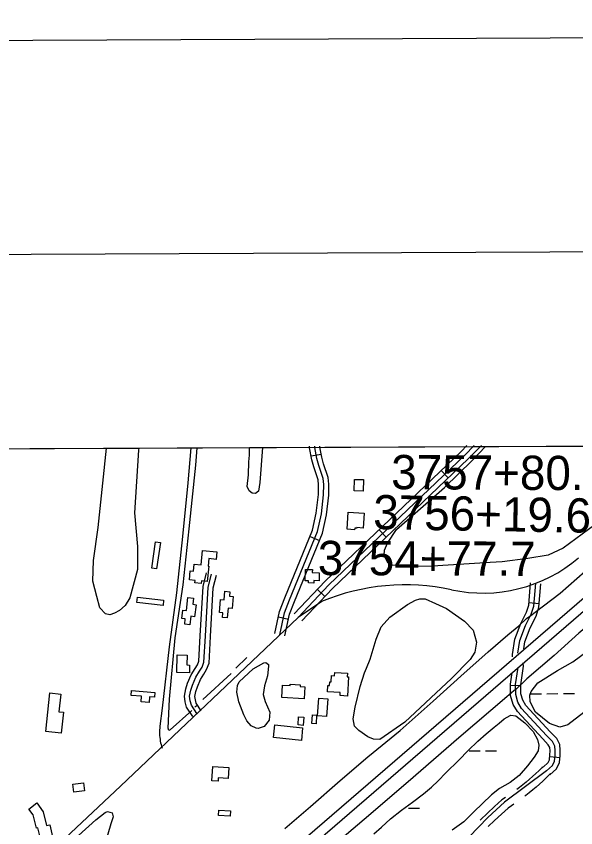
# Model space of a CAD drawing. Extents: x 3424494 to 3462436, y 522220 to 547718.
# Drawn here: x 3445950 to 3447583, y 544764 to 547135 of the extents above; entities that cross this region are included whole.
import ezdxf

# ---------------------------------------------------------------- set-up
doc = ezdxf.new("R2010")
doc.units = 0
for name, color, linetype in [('G-ANNO-NPLT', 7, 'Continuous'), ('V-ANNO-SYMB', 7, 'Continuous'), ('V-BLDG-OTLN', 7, 'Continuous'), ('V-GRID-FRAM', 7, 'Continuous'), ('V-LEVE-TOET', 7, 'Continuous'), ('V-RIVR-EDGE', 7, 'Continuous'), ('V-ROAD-CNTR', 7, 'Continuous'), ('V-SITE-VEGE', 7, 'Continuous'), ('V-SURV-IDEN', 7, 'Continuous'), ('V-SURV-LINE', 7, 'Continuous'), ('V-TOPO-SHOR', 7, 'Continuous'), ('V-WETL-SWMP', 7, 'Continuous')]:
    doc.layers.add(name, color=color, linetype=linetype)

msp = doc.modelspace()

# ---------------------------------------------------------------- linework, layer by layer
at = {"layer": 'G-ANNO-NPLT'}
msp.add_lwpolyline([(3425186.3, 522803.1), (3461852.6, 522968.4), (3461743.6, 547134.8), (3425077.3, 546969.5)], close=True, dxfattribs=at)
at = {"layer": 'V-ANNO-SYMB'}
msp.add_lwpolyline([(3427933.6, 523440.5), (3461016.5, 523589.7), (3460913.1, 546506), (3427830.3, 546356.9), (3427933.6, 523440.5)], dxfattribs=at)
at = {"layer": 'V-BLDG-OTLN'}
for points in [[(3446936.7, 545748.5), (3446937.5, 545781.8), (3446963.6, 545781.2), (3446962.8, 545747.9)], [(3446915.7, 545636.1), (3446919.1, 545686.4), (3446965.9, 545683.2), (3446963, 545639.6), (3446943.8, 545640.9), (3446943.7, 545638.9), (3446938.1, 545639.3), (3446937.8, 545634.6)], [(3446371, 545597.6), (3446359.4, 545520.3), (3446345.4, 545522.4), (3446357, 545599.7)], [(3446493.7, 545574), (3446535.6, 545569.8), (3446533.4, 545548.2), (3446512, 545550.4), (3446509.8, 545528.7), (3446512.3, 545528.4), (3446507.8, 545483.5), (3446490.6, 545485.2), (3446489.8, 545477.3), (3446471.1, 545479.2), (3446471.9, 545486.9), (3446455.6, 545488.5), (3446458.2, 545514.8), (3446467.4, 545513.9), (3446469.4, 545533.9), (3446489.4, 545531.8)], [(3446793.3, 545485.4), (3446794.1, 545518.9), (3446814.3, 545518.5), (3446814.1, 545509.5), (3446834.7, 545509), (3446834.1, 545486), (3446818.5, 545486.4), (3446818.4, 545478.8), (3446803.3, 545479.2), (3446803.4, 545485.2)], [(3446583.5, 545440), (3446580.4, 545404.6), (3446568.3, 545405.7), (3446565.8, 545377.6), (3446552, 545378.9), (3446553.2, 545392.5), (3446543.3, 545393.3), (3446546.6, 545430.7), (3446556.8, 545429.8), (3446559.1, 545455.1), (3446573.6, 545453.8), (3446572.5, 545441)], [(3446378.5, 545413.4), (3446302, 545422.3), (3446303.8, 545437.5), (3446380.3, 545428.6)], [(3446475, 545415.9), (3446470.8, 545380.8), (3446460.1, 545382.1), (3446457.1, 545357.3), (3446441.8, 545359.1), (3446443.6, 545374.5), (3446433.6, 545375.7), (3446436.6, 545400), (3446446.6, 545398.8), (3446451.1, 545436.6), (3446467.4, 545434.6), (3446465.4, 545417.1)], [(3446455.5, 545216.4), (3446418.5, 545217.4), (3446420, 545269.4), (3446448.9, 545268.6), (3446448.1, 545239.8), (3446456.1, 545239.6)], [(3446879.7, 545217.3), (3446916.7, 545215.5), (3446916.2, 545205.3), (3446919.4, 545205.1), (3446916.6, 545149.1), (3446895.4, 545150.1), (3446895.9, 545159.8), (3446858.8, 545161.7), (3446859.7, 545179.5), (3446864.7, 545179.3), (3446865.3, 545190.8), (3446869.1, 545190.6), (3446870, 545208.5), (3446879.2, 545208.1)], [(3446790.4, 545141.2), (3446725, 545145.2), (3446727.1, 545180.9), (3446749.3, 545179.5), (3446749.6, 545183.8), (3446778.9, 545182), (3446778.6, 545176.9), (3446792.5, 545176)], [(3446080.9, 545040.4), (3446036.1, 545045.4), (3446048.6, 545158.2), (3446080.3, 545154.7), (3446074.6, 545102.9), (3446087.7, 545101.4)], [(3446286.9, 545164.8), (3446355.1, 545159), (3446353.9, 545145.6), (3446339.4, 545146.9), (3446338, 545129.7), (3446314.3, 545131.7), (3446315.8, 545148.5), (3446285.8, 545151)], [(3446859.4, 545140.9), (3446856, 545089.5), (3446829.4, 545091.2), (3446832.8, 545142.7)], [(3446787.8, 545063.4), (3446772.5, 545064.4), (3446774.2, 545088), (3446789.4, 545086.9)], [(3446812.7, 545068.3), (3446814.3, 545093.6), (3446826.9, 545092.8), (3446825.3, 545067.6)], [(3446782.2, 545019.4), (3446701, 545027.8), (3446704.8, 545064.4), (3446786, 545056)], [(3446523.7, 544942.8), (3446570.7, 544939.9), (3446568.8, 544908.2), (3446539.7, 544910), (3446539.1, 544900.4), (3446521.2, 544901.5)], [(3446149.4, 544872), (3446117.9, 544868.6), (3446115.4, 544892), (3446146.9, 544895.4)], [(3446056, 544738), (3446022.1, 544728.9), (3446012.7, 544763.6), (3446009.2, 544762.7), (3445999.7, 544801.5), (3445987, 544818.8), (3446010.6, 544837.2), (3446029, 544810.7), (3446038.7, 544771.1), (3446048.4, 544773.2)], [(3446540.5, 544799.9), (3446541.3, 544815.4), (3446575, 544813.7), (3446574.2, 544798.2)]]:
    msp.add_lwpolyline(points, close=True, dxfattribs=at)
at = {"layer": 'V-GRID-FRAM'}
for points in [[(3428547.8, 545793.2), (3460200.7, 545935.9)], [(3428547.8, 545793.2), (3451467.1, 545896.5)]]:
    msp.add_lwpolyline(points, dxfattribs=at)
at = {"layer": 'V-LEVE-TOET'}
for points in [[(3446734.1, 544761.9), (3446808.8, 544826.2), (3446895.8, 544902.1), (3446976.1, 544971.6), (3447070.3, 545048.6), (3447166.5, 545134), (3447247.2, 545207.1), (3447327, 545278.2), (3447384.7, 545328.2), (3447416.5, 545354), (3447439.5, 545375.9), (3447451.8, 545384.6), (3447464.5, 545393.7), (3447537.3, 545449.3), (3447610.8, 545513.3), (3447692.3, 545585.1), (3447755.1, 545643.5), (3447831.4, 545714.2), (3447914, 545795.6), (3448001.9, 545879), (3448003.7, 545880.9)], [(3448177, 545881.7), (3448171.9, 545876.8), (3448060.2, 545782.3), (3448035.6, 545758.1), (3448021.3, 545739), (3448005.8, 545710.4), (3447991.9, 545685.8), (3447953.7, 545644.5), (3447873.8, 545571), (3447770.9, 545482), (3447709.3, 545429.6), (3447592.4, 545332.3), (3447519.7, 545267.2), (3447440.2, 545198.9), (3447431.5, 545190.1), (3447416.4, 545175.4), (3447410.4, 545170.3), (3447402.1, 545163.9), (3447381.8, 545146.8), (3447242.3, 545026.9), (3447093.7, 544898.2), (3446965.7, 544788.2), (3446817.5, 544663.1)]]:
    msp.add_lwpolyline(points, dxfattribs=at)
at = {"layer": 'V-RIVR-EDGE'}
msp.add_spline([(3449024.5, 545885.5), (3449019.3, 545873.5), (3449011.8, 545864), (3448999, 545850.5), (3448985, 545836.1), (3448976.3, 545824.5), (3448965.5, 545808.1), (3448951.4, 545790.8), (3448930.4, 545766.9), (3448908.8, 545733.6), (3448893.9, 545712.1), (3448877.4, 545692), (3448858.8, 545671.4), (3448838.9, 545650.8), (3448829.8, 545641), (3448822, 545628.2), (3448802.1, 545605.2), (3448785.1, 545578.4), (3448774, 545564.8), (3448769, 545560.7), (3448761.1, 545553.7), (3448753.7, 545540.1), (3448748.7, 545530.6), (3448741.3, 545522), (3448732.6, 545514.6), (3448730.5, 545510.9), (3448729.7, 545504.3), (3448730.5, 545498.5), (3448726.4, 545491.9), (3448714, 545480.8), (3448695.8, 545464.4), (3448686.3, 545455.7), (3448680.1, 545452.4), (3448668.5, 545431.4), (3448642, 545397.3), (3448623, 545372.2), (3448598.5, 545341.7), (3448586.1, 545326.9), (3448567.5, 545299.7), (3448554.3, 545276.7), (3448543.5, 545261), (3448535.2, 545255.3), (3448529.4, 545249.1), (3448514.6, 545229.3), (3448492.2, 545191.9), (3448480.6, 545178.7), (3448457.5, 545153.6), (3448442.1, 545135.1), (3448424.4, 545110.8), (3448410.3, 545090.6), (3448392.9, 545075.8), (3448377.6, 545060.6), (3448361.1, 545040.4), (3448350.7, 545027.7), (3448339.1, 545005.8), (3448331.3, 544993.5), (3448317.6, 544978.7), (3448303.6, 544960.5), (3448289.9, 544948.2), (3448280, 544931.7), (3448265.1, 544908.3), (3448249.8, 544884), (3448245.2, 544876.6), (3448244.4, 544872.9), (3448244.4, 544867.1), (3448242.3, 544863.4), (3448237.7, 544861.3), (3448234.4, 544856.8), (3448231.1, 544846.5), (3448224.9, 544842), (3448220.4, 544838.3), (3448221.6, 544830.8), (3448219.1, 544824.3), (3448214.5, 544819.7), (3448208.8, 544818.9), (3448205.5, 544816.4), (3448194.7, 544800.4), (3448196.4, 544802), (3448189.7, 544791.3), (3448179.4, 544775.7), (3448174, 544768.7), (3448167.4, 544757.2), (3448157.4, 544744.4), (3448145.4, 544730.8), (3448135.1, 544715.2), (3448124.8, 544701.2), (3448119.4, 544699.9), (3448113.2, 544693), (3448107.4, 544682.7), (3448106.1, 544678.9), (3448100.3, 544665.8), (3448092.9, 544652.2), (3448086.3, 544642.3), (3448078.8, 544638.2), (3448075.5, 544633.2), (3448067.2, 544618.8), (3448046.1, 544585.9), (3448037.4, 544569.4), (3448028.3, 544560.4), (3448024.6, 544560), (3448021.7, 544557.1), (3448012.6, 544541.4), (3448005.1, 544530.7), (3447995.6, 544524.6), (3447994.8, 544522.1), (3447994.4, 544515.5), (3447992.3, 544513.4), (3447987, 544513), (3447986.9, 544505.6), (3447985.7, 544501.9), (3447978.3, 544497.8), (3447969.6, 544490), (3447961.3, 544476.4), (3447954.7, 544466.9), (3447950.1, 544453.7), (3447948, 544444.7), (3447946.4, 544440.1), (3447940.2, 544435.2), (3447932.3, 544427.8), (3447921.6, 544414.6), (3447905.4, 544390.8), (3447884.7, 544360.7), (3447854.9, 544322.4), (3447838, 544301.8), (3447830.9, 544294), (3447828, 544286.2), (3447823.9, 544273.8), (3447817.7, 544265.2), (3447807.7, 544251.6), (3447798.6, 544239.7), (3447792, 544235.1), (3447787.5, 544230.2), (3447785.4, 544227.7), (3447783.7, 544218.3), (3447781.7, 544216.2), (3447776.3, 544210.9), (3447766.4, 544194.8), (3447753.1, 544178.7), (3447722.9, 544136.3), (3447707.6, 544119.1), (3447694.8, 544104.2), (3447681.1, 544084.1), (3447673.7, 544073.8), (3447667, 544060.6), (3447657.1, 544050.3), (3447653.8, 544047.4), (3447652.2, 544044.1), (3447650.1, 544037.5), (3447645.5, 544031.8), (3447640.2, 544026.8), (3447633.1, 544020.3), (3447624.9, 544014.5), (3447616.6, 544013.7), (3447613.3, 544010), (3447605, 544000.9), (3447598.8, 543989), (3447590.1, 543972.9), (3447575.6, 543949.5), (3447562.4, 543928.5), (3447550.8, 543912), (3447539.6, 543898), (3447530.9, 543888.1), (3447527.6, 543882.8), (3447525.5, 543874.1), (3447521.8, 543870.4), (3447516, 543864.7), (3447515.2, 543861), (3447514.8, 543854.8), (3447509.8, 543851.1), (3447503.2, 543848.2), (3447495.3, 543829.7), (3447484.6, 543819), (3447471.8, 543804.1), (3447462.7, 543795.1), (3447454, 543781.9), (3447440.3, 543762.2), (3447430.4, 543746.5), (3447426.2, 543740.3), (3447424.1, 543732.1), (3447421.7, 543729.2), (3447414.2, 543721.8), (3447406, 543717.3), (3447398.5, 543709.9), (3447394, 543701.2), (3447391.1, 543696.3), (3447384, 543692.2), (3447379.5, 543687.7), (3447373.7, 543676.1), (3447366.2, 543663.8), (3447360.4, 543649.4), (3447357.9, 543636.6), (3447352.5, 543628.8), (3447345.1, 543626.7), (3447341.4, 543623), (3447336.4, 543618.5), (3447328.2, 543607.8), (3447317, 543591.3), (3447306.2, 543572.8), (3447293.8, 543548.9), (3447283.4, 543532), (3447267.3, 543508.1), (3447258.6, 543503.6), (3447254.1, 543498.7), (3447252, 543493.7), (3447247.4, 543485.9), (3447242.1, 543476.8), (3447234.2, 543467), (3447228.4, 543461.6), (3447225.1, 543458.3), (3447223.9, 543452.6), (3447222.6, 543443.9), (3447217.6, 543437.3), (3447211, 543429.9), (3447197.4, 543418.4), (3447193.6, 543413), (3447188.7, 543405.6), (3447177.5, 543390.8), (3447165.1, 543376), (3447155.2, 543362), (3447143.6, 543347.6), (3447132.4, 543332), (3447125.4, 543325.4), (3447119.6, 543316.7), (3447107.2, 543302.3), (3447099.3, 543290), (3447082.4, 543268.2), (3447069.5, 543250.5), (3447056.7, 543231.5), (3447044.7, 543214.2), (3447030.6, 543189.1), (3447016.9, 543167.7), (3447008.7, 543152), (3446997.5, 543133.1), (3446988.4, 543122.4), (3446978.9, 543109.6), (3446965.6, 543092.3), (3446951.1, 543073), (3446946.6, 543071.8), (3446942.5, 543067.7), (3446932.1, 543057), (3446914.3, 543030.2)], degree=3, dxfattribs=at)
at = {"layer": 'V-ROAD-CNTR'}
for p, q in [((3446810.4, 545850.4), (3446839.9, 545855.7)), ((3447210.7, 545786), (3447189.9, 545807.7)), ((3447030, 545613.2), (3447009.3, 545634.8)), ((3446807.5, 545615.1), (3446835.3, 545603.7)), ((3446851.1, 545439.7), (3446829.3, 545460.4)), ((3447446.6, 545422.2), (3447476.6, 545419.7)), ((3446715.4, 545380.1), (3446744.7, 545373.8)), ((3447392.7, 545180.1), (3447422.7, 545180.3)), ((3447507.2, 544972.7), (3447537.1, 544969.8))]:
    msp.add_line(p, q, dxfattribs=at)
for points in [[(3446459.4, 545873.9), (3446451.4, 545772.2), (3446435.3, 545615.4), (3446418.3, 545450), (3446396.3, 545292.4), (3446376.2, 545113.6), (3446369.5, 545060.6), (3446368.9, 545055.2), (3446368.5, 545049.8), (3446368.4, 545044.4), (3446368.4, 545039), (3446368.7, 545033.7), (3446369.1, 545028.3), (3446369.8, 545022.9), (3446370.6, 545017.6), (3446371.6, 545012.3), (3446372.8, 545007.1), (3446374.3, 545001.9), (3446375.9, 544996.8)], [(3446704.8, 545331.3), (3446718.8, 545396.3), (3446734, 545436), (3446815.1, 545633.6), (3446825.9, 545683.6), (3446832.3, 545737.7), (3446832.7, 545766.4), (3446831, 545780.7), (3446818.7, 545818.2), (3446812.4, 545839.4), (3446806.2, 545874), (3446806.3, 545878.7)], [(3446719.5, 545328.1), (3446733.3, 545392), (3446748, 545430.4), (3446829.5, 545629.2), (3446840.7, 545681.1), (3446847.2, 545736.8), (3446847.7, 545767.2), (3446845.7, 545784), (3446833, 545822.7), (3446827, 545842.9), (3446821.2, 545875.2), (3446821.3, 545878.8)], [(3446734.1, 545324.9), (3446747.7, 545387.7), (3446761.9, 545424.9), (3446843.9, 545624.7), (3446855.5, 545678.6), (3446862.2, 545735.8), (3446862.7, 545767.9), (3446860.4, 545787.2), (3446847.3, 545827.1), (3446841.6, 545846.3), (3446836.2, 545876.4), (3446836.3, 545878.9)], [(3447265.6, 545880.8), (3447248.5, 545863.7), (3446852.2, 545484.6), (3446761.6, 545388.9)], [(3447286.9, 545880.9), (3447259, 545853), (3446862.9, 545474), (3446772.5, 545378.5)], [(3447308.2, 545881), (3447269.5, 545842.3), (3446873.5, 545463.4), (3446783.4, 545368.2)], [(3446465.1, 545089.5), (3446447.2, 545116.3), (3446443.4, 545132.2), (3446441, 545148.7), (3446445.5, 545169.6), (3446450.4, 545186.2), (3446460.8, 545211.2), (3446472, 545229.2), (3446479, 545240.2), (3446483.2, 545251.3), (3446487.2, 545324.8), (3446495.6, 545469.2), (3446505.9, 545509.2)], [(3446477.6, 545097.8), (3446461.2, 545122.4), (3446458.2, 545135), (3446456.2, 545148.2), (3446460, 545165.9), (3446464.5, 545181.1), (3446474.2, 545204.3), (3446484.7, 545221.3), (3446492.4, 545233.5), (3446498, 545248.2), (3446502.2, 545324), (3446510.5, 545466.9), (3446520.4, 545505.4)], [(3446490.1, 545106.1), (3446475.1, 545128.5), (3446472.9, 545137.8), (3446471.5, 545147.6), (3446474.6, 545162.2), (3446478.7, 545176.1), (3446487.6, 545197.4), (3446497.5, 545213.3), (3446505.9, 545226.7), (3446512.9, 545245), (3446517.2, 545323.1), (3446525.3, 545464.6), (3446534.9, 545501.7)], [(3447398.9, 545264), (3447398.6, 545270.2), (3447405.4, 545315), (3447422.6, 545360.6), (3447439.4, 545393.8), (3447446, 545414.5), (3447451.3, 545479.6)], [(3447414.4, 545274.2), (3447420, 545311.2), (3447436.4, 545354.6), (3447453.3, 545388.1), (3447460.8, 545411.5), (3447466.2, 545478.4)], [(3447431.5, 545287), (3447434.6, 545307.4), (3447450.1, 545348.5), (3447467.2, 545382.3), (3447475.6, 545408.6), (3447481.2, 545477.1)], [(3446841.6, 545425), (3446772.5, 545378.5), (3446254.6, 544885.5), (3446060.9, 544703.3)], [(3447497.7, 544930.4), (3447514.9, 544945.7), (3447520.9, 544958.4), (3447522.6, 544975.9), (3447523, 544990), (3447521.7, 545002.9), (3447515.3, 545015.7), (3447497.9, 545033.8), (3447425.2, 545112.4), (3447414.3, 545130.7), (3447407.8, 545153), (3447407.6, 545182.5), (3447414.7, 545232.6)], [(3447507.6, 544919.2), (3447527.1, 544936.5), (3447535.6, 544954.4), (3447537.6, 544975), (3447538, 544990.5), (3447536.4, 545007.1), (3447527.7, 545024.5), (3447508.8, 545044.1), (3447437.3, 545121.4), (3447428.2, 545136.8), (3447422.8, 545155.2), (3447422.6, 545181.5), (3447430.4, 545236.4), (3447429.9, 545245.9)], [(3447487.7, 544941.6), (3447502.6, 544954.9), (3447506.2, 544962.5), (3447507.6, 544976.9), (3447508, 544989.4), (3447507.1, 544998.7), (3447502.9, 545006.9), (3447486.9, 545023.5), (3447413.2, 545103.4), (3447400.5, 545124.7), (3447392.9, 545150.8), (3447392.6, 545183.5), (3447397.4, 545217.6)], [(3447497.7, 544930.4), (3447374.8, 544839.4), (3447326.3, 544793.8), (3447217.6, 544681.4), (3447189.2, 544642.7), (3447140.6, 544599.1), (3447087.8, 544539.5), (3447056.1, 544498.6), (3447013.2, 544453.4), (3446987.5, 544427.4), (3446952.6, 544404), (3446894, 544366.9), (3446872.3, 544354.9)], [(3447486.2, 544941.7), (3447486.2, 544941.7), (3447484, 544939.3), (3447475.4, 544930.9), (3447466.4, 544922.3), (3447457.2, 544914), (3447447.8, 544905.7), (3447438.3, 544897.7), (3447428.7, 544889.8), (3447418.9, 544882.1), (3447410.9, 544876.1)], [(3447509.6, 544922.9), (3447509.1, 544922.3), (3447505.7, 544918.5), (3447496.2, 544909.2), (3447486.8, 544900.3), (3447477.2, 544891.6), (3447467.4, 544883), (3447457.5, 544874.6), (3447447.5, 544866.4), (3447437.3, 544858.4), (3447434.9, 544856.6)], [(3447378.3, 544853), (3447366.9, 544845.6), (3447345.6, 544825.9), (3447325.2, 544806.9), (3447305.1, 544787.7), (3447303.9, 544786.5)], [(3447402.5, 544833.1), (3447395.1, 544828.2), (3447385.4, 544821.8), (3447366, 544803.9), (3447345.8, 544785.1), (3447327.4, 544767.5)]]:
    msp.add_lwpolyline(points, dxfattribs=at)
for centre, radius, start, end in [((3447311.7, 545880.9), 431.2, 257.7647, 310.4335), ((3447086, 544836.9), 636.9, 77.8292, 112.5736)]:
    msp.add_arc(centre, radius, start, end, dxfattribs=at)
at = {"layer": 'V-SITE-VEGE'}
for p, q in [((3446203.3, 545770.9), (3446213.3, 545872.8)), ((3446213.3, 545872.8), (3446307.6, 545873.3)), ((3446307.6, 545873.3), (3446307.1, 545866.8)), ((3446630.5, 545852.7), (3446631, 545874.7)), ((3446631, 545874.7), (3446668.6, 545874.9)), ((3446668.6, 545874.9), (3446661.1, 545773.2)), ((3447280.5, 545837.1), (3447319.9, 545877.8)), ((3447319.9, 545877.8), (3447902.9, 545880.4)), ((3446307.1, 545866.8), (3446295.2, 545684.5)), ((3446628.9, 545833), (3446630.5, 545852.7)), ((3446628.1, 545795.3), (3446628.9, 545833)), ((3447200.4, 545757.7), (3447280.5, 545837.1)), ((3446624.1, 545761.4), (3446628.1, 545795.3)), ((3446661.1, 545773.2), (3446657.2, 545747.3)), ((3446189.1, 545641.3), (3446203.3, 545770.9)), ((3446629.6, 545748.1), (3446624.1, 545761.4)), ((3447059.7, 545635.2), (3447200.4, 545757.7)), ((3446639.1, 545741.8), (3446629.6, 545748.1)), ((3446648.5, 545741), (3446639.1, 545741.8)), ((3446657.2, 545747.3), (3446648.5, 545741)), ((3446295.2, 545684.5), (3446303.8, 545585.5)), ((3446175.7, 545545.4), (3446189.1, 545641.3)), ((3447033.7, 545595.1), (3447059.7, 545635.2)), ((3447644.5, 545653.4), (3447546.2, 545581.1)), ((3446303.8, 545585.5), (3446303.8, 545518.7)), ((3447025.1, 545574.7), (3447033.7, 545595.1)), ((3447024.3, 545560.5), (3447025.1, 545574.7)), ((3447034.5, 545538.5), (3447024.3, 545560.5)), ((3447502.2, 545560.7), (3447443.3, 545550.5)), ((3447546.2, 545581.1), (3447502.2, 545560.7)), ((3446173.4, 545484.1), (3446175.7, 545545.4)), ((3447048.6, 545531.4), (3447034.5, 545538.5)), ((3447333.1, 545539.2), (3447164.9, 545528.3)), ((3447368.6, 545541.1), (3447333.1, 545539.2)), ((3447443.3, 545550.5), (3447368.6, 545541.1)), ((3446303.8, 545518.7), (3446281.8, 545435.4)), ((3447088.7, 545527.5), (3447048.6, 545531.4)), ((3447164.9, 545528.3), (3447088.7, 545527.5)), ((3446185.1, 545440.1), (3446173.4, 545484.1)), ((3446194.6, 545407.1), (3446185.1, 545440.1)), ((3446281.8, 545435.4), (3446268.4, 545413.4)), ((3446210.3, 545389), (3446194.6, 545407.1)), ((3446251.1, 545398.4), (3446237, 545390.6)), ((3446268.4, 545413.4), (3446251.1, 545398.4)), ((3446223.6, 545385.9), (3446210.3, 545389)), ((3446237, 545390.6), (3446223.6, 545385.9))]:
    msp.add_line(p, q, dxfattribs=at)
for points in [[(3446982.7, 545257.1), (3447000.8, 545315.3), (3447014.9, 545351.5), (3447040.9, 545379), (3447092.1, 545416), (3447115.7, 545428.6), (3447128.2, 545433.3), (3447144, 545432.5), (3447173.9, 545419.1), (3447206.1, 545404.9), (3447258.8, 545367.9), (3447283.2, 545341.2), (3447293.4, 545306.6), (3447288.7, 545276.7), (3447275.3, 545256.2), (3447220.2, 545200.4), (3447084.1, 545073), (3447010.9, 545021.9), (3446992.8, 545022.7), (3446976.3, 545029.8), (3446949.6, 545047.9), (3446937.8, 545060.5), (3446933.8, 545082.5), (3446939.4, 545116.3), (3446953.5, 545176.9), (3446966.9, 545217), (3446972.4, 545230.4)], [(3446614.5, 545093.6), (3446599.6, 545132.2), (3446594.1, 545160.5), (3446595.6, 545180.2), (3446600.4, 545190.4), (3446641.3, 545228.1), (3446672.7, 545246.2), (3446678.2, 545247), (3446686.1, 545241.5), (3446686.1, 545236), (3446683, 545207.7), (3446675.1, 545178.6), (3446671.1, 545153.4), (3446676.6, 545132.9), (3446690, 545102.3), (3446688.4, 545078.7), (3446673.5, 545059.8), (3446656.2, 545054.3), (3446649.9, 545055.1), (3446635.7, 545062.2), (3446623.1, 545076.3)]]:
    msp.add_lwpolyline(points, close=True, dxfattribs=at)
msp.add_lwpolyline([(3446101.5, 544714.7), (3446182.5, 544787), (3446210.1, 544809), (3446216.4, 544811.4), (3446229.7, 544808.2), (3446232.9, 544796.4), (3446226.6, 544776), (3446210.8, 544722.5)], dxfattribs=at)
at = {"layer": 'V-SURV-LINE'}
for points in [[(3445808.1, 543883.4), (3447812.6, 545614.3)], [(3447832.2, 545591.6), (3445827.7, 543860.7)]]:
    msp.add_lwpolyline(points, dxfattribs=at)
at = {"layer": 'V-TOPO-SHOR'}
for p, q in [((3446623.5, 545261.2), (3446591.2, 545230.1)), ((3446577, 545214.8), (3446495.1, 545138.8)), ((3446477, 545120.7), (3446471.8, 545116.3))]:
    msp.add_line(p, q, dxfattribs=at)
msp.add_lwpolyline([(3446462.8, 545106.5), (3446399.7, 545049.8), (3446395.8, 545048.6), (3446393.8, 545054.9), (3446397.8, 545140), (3446413.6, 545318.8), (3446437.3, 545474), (3446454.7, 545637), (3446474.5, 545823.3), (3446478.4, 545874)], dxfattribs=at)
at = {"layer": 'V-WETL-SWMP'}
for p, q in [((3447574.6, 545249.3), (3447615.5, 545279.2)), ((3447529.7, 545223.4), (3447574.6, 545249.3)), ((3447472.3, 545187.2), (3447529.7, 545223.4)), ((3447452.6, 545162.1), (3447472.3, 545187.2)), ((3447448.7, 545151.8), (3447452.6, 545162.1)), ((3447547, 545156.1), (3447579, 545156.2)), ((3447450.3, 545132.2), (3447448.7, 545151.8)), ((3447451, 545155.6), (3447483, 545155.8)), ((3447499, 545155.9), (3447531, 545156)), ((3447466, 545101.5), (3447450.3, 545132.2)), ((3447506.9, 545069.2), (3447466, 545101.5)), ((3447606.8, 545100.7), (3447559.6, 545065.3)), ((3447536.8, 545058.2), (3447506.9, 545069.2)), ((3447559.6, 545065.3), (3447536.8, 545058.2)), ((3447271.8, 544988.7), (3447303.8, 544988.8)), ((3447319.8, 544988.9), (3447351.8, 544989)), ((3447094.6, 544821.4), (3447126.6, 544821.5))]:
    msp.add_line(p, q, dxfattribs=at)
for points in [[(3447269.3, 544989.8), (3447297.7, 545016.7), (3447321.4, 545038.3), (3447344.7, 545058.4), (3447359.7, 545069.9), (3447374.6, 545082.1), (3447392, 545092.3), (3447393.2, 545093.5), (3447408.6, 545091.5), (3447434.6, 545071), (3447459, 545045), (3447471.2, 545021.7), (3447475.6, 545005.2), (3447473.6, 544989.4), (3447462.1, 544970.1), (3447442, 544944.8), (3447417.6, 544917.2), (3447391.5, 544896), (3447360.4, 544879), (3447337.1, 544860.1), (3447310.3, 544834.1), (3447286.2, 544811.6), (3447256.2, 544781.3), (3447222.3, 544756.8)], [(3446993.6, 544746.7), (3447015.7, 544766), (3447042.5, 544790.5), (3447074.5, 544815.7), (3447106.8, 544839), (3447138.8, 544863), (3447162, 544882.7), (3447181.8, 544901.6), (3447203.8, 544924.6), (3447241.7, 544961.5), (3447269.3, 544989.8)]]:
    msp.add_lwpolyline(points, dxfattribs=at)
msp.add_arc((3447242.9, 544771.8), 35.2, 40.803, 41.0302, dxfattribs=at)

# ---------------------------------------------------------------- texts
at = {"layer": 'V-SURV-IDEN'}
for s, rotation, p in [('3757+80.8', 359.6877, (3447044.2, 545753.4)), ('3756+19.6', 359.0459, (3446991.3, 545636.6)), ('3754+77.7', 359.7698, (3446830.1, 545502.4))]:
    msp.add_text(s, height=100, rotation=rotation, dxfattribs=at).set_placement(p)

doc.saveas('drawing.dxf')
